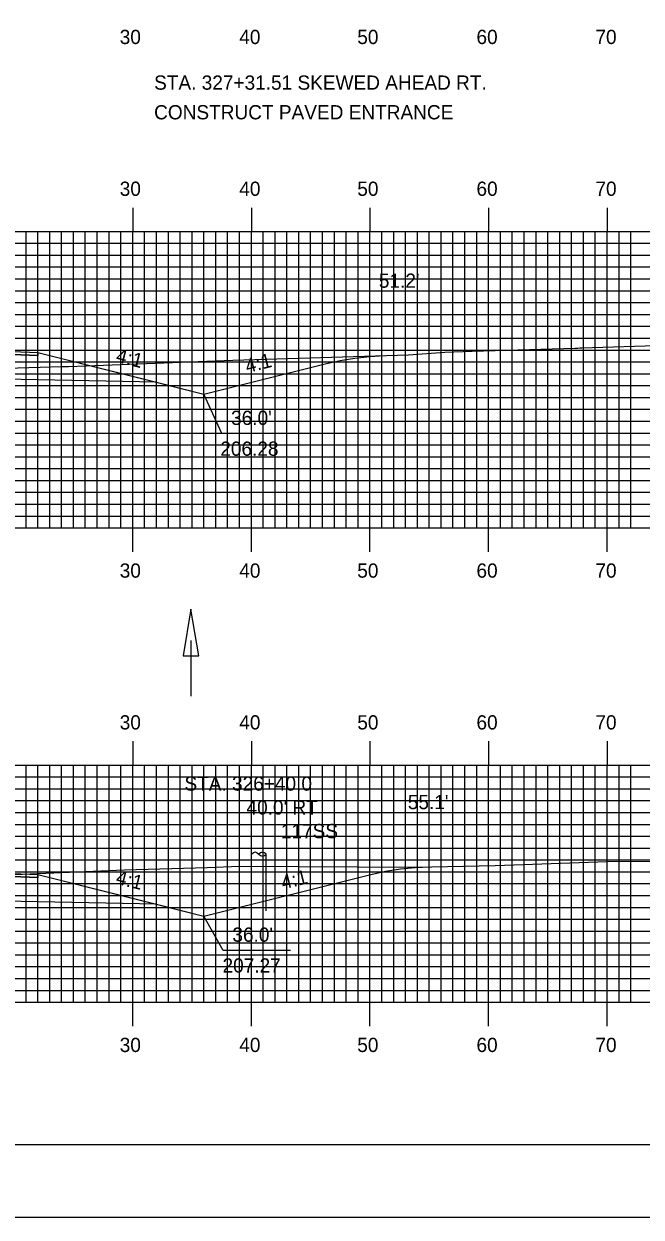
# Model space of a CAD drawing. Extents: x 1821605 to 1821948, y 442591 to 442811.
# Drawn here: x 1821791.6 to 1821843.6, y 442590.5 to 442691.2 of the extents above; entities that cross this region are included whole.
import ezdxf

# ---------------------------------------------------------------- set-up
doc = ezdxf.new("R2010")
doc.units = 0
for name, color, linetype in [('ANNOTATION', 7, 'Continuous'), ('BORDER', 7, 'Continuous'), ('D_Drainage_Ditch_Line', 7, 'Continuous'), ('D_Drainage_Text', 7, 'Continuous'), ('D_Roadway_Centerline', 7, 'Continuous'), ('D_Roadway_Edge_Shoulder', 7, 'Continuous'), ('D_Roadway_SlopeLines', 7, 'Continuous'), ('D_Roadway_SubGrade', 7, 'Continuous'), ('D_Text_Standard', 7, 'Continuous'), ('D_Utilities_Pole_Joint', 7, 'Continuous'), ('H_V ANNOTATION', 7, 'Continuous'), ('MAJOR', 7, 'Continuous'), ('MINOR', 7, 'Continuous'), ('PLOT BOUNDARY', 7, 'Continuous'), ('S_Roadway_Centerline', 7, 'Continuous')]:
    doc.layers.add(name, color=color, linetype=linetype)

msp = doc.modelspace()

# ---------------------------------------------------------------- linework, layer by layer
at = {"layer": 'ANNOTATION'}
for points in [[(1821813.95, 442656.62), (1821808.26, 442656.62), (1821806.74, 442659.95)], [(1821814.05, 442613.04), (1821808.36, 442613.04), (1821806.74, 442615.93)]]:
    msp.add_lwpolyline(points, dxfattribs=at)
at = {"layer": 'BORDER'}
msp.add_lwpolyline([(1821621.14, 442596.67), (1821941.14, 442596.67), (1821941.14, 442806.67), (1821621.14, 442806.67)], close=True, dxfattribs=at)
at = {"layer": 'D_Drainage_Ditch_Line'}
msp.add_line((1821805.65, 442639.18), (1821805.65, 442634.48), dxfattribs=at)
msp.add_lwpolyline([(1821805, 442637.87), (1821806.31, 442637.87), (1821805.65, 442641.81)], close=True, dxfattribs=at)
at = {"layer": 'D_Roadway_Centerline'}
for points in [[(1821726.4, 442659.78), (1821730.4, 442660.78), (1821740.74, 442663.37), (1821746.74, 442663.61), (1821770.74, 442664.09), (1821782.74, 442663.85), (1821792.74, 442663.45), (1821802.74, 442660.95), (1821806.74, 442659.95), (1821816.97, 442662.5), (1821818.22, 442662.78), (1821819.47, 442662.99), (1821820.72, 442663.13), (1821821.97, 442663.21)], [(1821726.4, 442615.77), (1821730.4, 442616.77), (1821740.74, 442619.35), (1821746.74, 442619.59), (1821770.74, 442620.07), (1821782.74, 442619.83), (1821792.74, 442619.43), (1821802.74, 442616.93), (1821806.74, 442615.93), (1821820.81, 442619.45), (1821822.06, 442619.72), (1821823.31, 442619.92), (1821824.56, 442620.04), (1821825.81, 442620.09)]]:
    msp.add_lwpolyline(points, dxfattribs=at)
at = {"layer": 'D_Roadway_Edge_Shoulder'}
for points in [[(1821782.74, 442663.85), (1821792.74, 442663.45), (1821792.74, 442663.2), (1821782.74, 442663.6)], [(1821782.74, 442619.83), (1821792.74, 442619.43), (1821792.74, 442619.18), (1821782.74, 442619.58)]]:
    msp.add_lwpolyline(points, close=True, dxfattribs=at)
at = {"layer": 'D_Roadway_SlopeLines'}
for points in [[(1821792.74, 442663.45), (1821806.74, 442659.95)], [(1821806.74, 442659.95), (1821816.97, 442662.5), (1821818.22, 442662.78), (1821819.47, 442662.99), (1821820.72, 442663.13), (1821821.97, 442663.21)], [(1821792.74, 442619.43), (1821806.74, 442615.93)], [(1821806.74, 442615.93), (1821820.81, 442619.45), (1821822.06, 442619.72), (1821823.31, 442619.92), (1821824.56, 442620.04), (1821825.81, 442620.09)]]:
    msp.add_lwpolyline(points, dxfattribs=at)
at = {"layer": 'D_Roadway_SubGrade'}
for points in [[(1821746.74, 442661.11), (1821730.4, 442660.78), (1821740.74, 442663.37), (1821740.74, 442663.12), (1821746.74, 442663.36), (1821770.74, 442663.84), (1821782.74, 442663.6), (1821792.74, 442663.2), (1821792.74, 442663.45), (1821802.74, 442660.95), (1821782.74, 442661.35), (1821770.74, 442661.59)], [(1821746.74, 442617.09), (1821730.4, 442616.77), (1821740.74, 442619.35), (1821740.74, 442619.1), (1821746.74, 442619.34), (1821770.74, 442619.82), (1821782.74, 442619.58), (1821792.74, 442619.18), (1821792.74, 442619.43), (1821802.74, 442616.93), (1821782.74, 442617.33), (1821770.74, 442617.57)]]:
    msp.add_lwpolyline(points, close=True, dxfattribs=at)
at = {"layer": 'D_Utilities_Pole_Joint'}
for p, q in [((1821810.74, 442621.15), (1821810.9, 442621.26)), ((1821811.21, 442621.26), (1821811.37, 442621.15)), ((1821811.52, 442621.26), (1821811.37, 442621.15)), ((1821811.99, 442621.15), (1821811.84, 442621.26)), ((1821810.74, 442616.39), (1821810.74, 442621.15)), ((1821811.37, 442621.15), (1821811.52, 442621.04)), ((1821811.84, 442621.04), (1821811.99, 442621.15)), ((1821811.99, 442616.39), (1821811.99, 442621.15))]:
    msp.add_line(p, q, dxfattribs=at)
for centre, start, end in [((1821811.06, 442621.04), 90, 125.2644), ((1821811.06, 442621.04), 54.7356, 90), ((1821811.68, 442621.04), 90, 125.2644), ((1821811.68, 442621.04), 54.7356, 90), ((1821811.68, 442621.26), 234.7356, 270), ((1821811.68, 442621.26), 270, 305.2644)]:
    msp.add_arc(centre, 0.271, start, end, dxfattribs=at)
at = {"layer": 'MAJOR'}
for p, q in [((1821800.74, 442675.67), (1821800.74, 442673.67)), ((1821810.74, 442675.67), (1821810.74, 442673.67)), ((1821820.74, 442675.67), (1821820.74, 442673.67)), ((1821830.74, 442675.67), (1821830.74, 442673.67)), ((1821840.74, 442675.67), (1821840.74, 442673.67)), ((1821630.74, 442673.67), (1821910.74, 442673.67)), ((1821630.74, 442673.67), (1821910.74, 442673.67)), ((1821800.74, 442648.67), (1821800.74, 442673.67)), ((1821810.74, 442648.67), (1821810.74, 442673.67)), ((1821820.74, 442648.67), (1821820.74, 442673.67)), ((1821830.74, 442648.67), (1821830.74, 442673.67)), ((1821840.74, 442648.67), (1821840.74, 442673.67)), ((1821630.74, 442668.67), (1821910.74, 442668.67)), ((1821630.74, 442663.67), (1821910.74, 442663.67)), ((1821630.74, 442658.67), (1821910.74, 442658.67)), ((1821630.74, 442653.67), (1821910.74, 442653.67)), ((1821630.74, 442648.67), (1821910.74, 442648.67)), ((1821630.74, 442648.67), (1821910.74, 442648.67)), ((1821800.74, 442646.66), (1821800.74, 442648.67)), ((1821810.74, 442646.66), (1821810.74, 442648.67)), ((1821820.74, 442646.66), (1821820.74, 442648.67)), ((1821830.74, 442646.66), (1821830.74, 442648.67)), ((1821840.74, 442646.66), (1821840.74, 442648.67)), ((1821800.74, 442630.67), (1821800.74, 442628.67)), ((1821810.74, 442630.67), (1821810.74, 442628.67)), ((1821820.74, 442630.67), (1821820.74, 442628.67)), ((1821830.74, 442630.67), (1821830.74, 442628.67)), ((1821840.74, 442630.67), (1821840.74, 442628.67)), ((1821630.74, 442628.67), (1821910.74, 442628.67)), ((1821630.74, 442628.67), (1821910.74, 442628.67)), ((1821800.74, 442608.67), (1821800.74, 442628.67)), ((1821810.74, 442608.67), (1821810.74, 442628.67)), ((1821820.74, 442608.67), (1821820.74, 442628.67)), ((1821830.74, 442608.67), (1821830.74, 442628.67)), ((1821840.74, 442608.67), (1821840.74, 442628.67)), ((1821630.74, 442623.67), (1821910.74, 442623.67)), ((1821630.74, 442618.67), (1821910.74, 442618.67)), ((1821630.74, 442613.67), (1821910.74, 442613.67)), ((1821630.74, 442608.67), (1821910.74, 442608.67)), ((1821630.74, 442608.67), (1821910.74, 442608.67)), ((1821800.74, 442606.66), (1821800.74, 442608.67)), ((1821810.74, 442606.66), (1821810.74, 442608.67)), ((1821820.74, 442606.66), (1821820.74, 442608.67)), ((1821830.74, 442606.66), (1821830.74, 442608.67)), ((1821840.74, 442606.66), (1821840.74, 442608.67))]:
    msp.add_line(p, q, dxfattribs=at)
at = {"layer": 'MINOR'}
for p, q in [((1821791.74, 442648.67), (1821791.74, 442673.67)), ((1821792.74, 442648.67), (1821792.74, 442673.67)), ((1821793.74, 442648.67), (1821793.74, 442673.67)), ((1821794.74, 442648.67), (1821794.74, 442673.67)), ((1821795.74, 442648.67), (1821795.74, 442673.67)), ((1821796.74, 442648.67), (1821796.74, 442673.67)), ((1821797.74, 442648.67), (1821797.74, 442673.67)), ((1821798.74, 442648.67), (1821798.74, 442673.67)), ((1821799.74, 442648.67), (1821799.74, 442673.67)), ((1821801.74, 442648.67), (1821801.74, 442673.67)), ((1821802.74, 442648.67), (1821802.74, 442673.67)), ((1821803.74, 442648.67), (1821803.74, 442673.67)), ((1821804.74, 442648.67), (1821804.74, 442673.67)), ((1821805.74, 442648.67), (1821805.74, 442673.67)), ((1821806.74, 442648.67), (1821806.74, 442673.67)), ((1821807.74, 442648.67), (1821807.74, 442673.67)), ((1821808.74, 442648.67), (1821808.74, 442673.67)), ((1821809.74, 442648.67), (1821809.74, 442673.67)), ((1821811.74, 442648.67), (1821811.74, 442673.67)), ((1821812.74, 442648.67), (1821812.74, 442673.67)), ((1821813.74, 442648.67), (1821813.74, 442673.67)), ((1821814.74, 442648.67), (1821814.74, 442673.67)), ((1821815.74, 442648.67), (1821815.74, 442673.67)), ((1821816.74, 442648.67), (1821816.74, 442673.67)), ((1821817.74, 442648.67), (1821817.74, 442673.67)), ((1821818.74, 442648.67), (1821818.74, 442673.67)), ((1821819.74, 442648.67), (1821819.74, 442673.67)), ((1821821.74, 442648.67), (1821821.74, 442673.67)), ((1821822.74, 442648.67), (1821822.74, 442673.67)), ((1821823.74, 442648.67), (1821823.74, 442673.67)), ((1821824.74, 442648.67), (1821824.74, 442673.67)), ((1821825.74, 442648.67), (1821825.74, 442673.67)), ((1821826.74, 442648.67), (1821826.74, 442673.67)), ((1821827.74, 442648.67), (1821827.74, 442673.67)), ((1821828.74, 442648.67), (1821828.74, 442673.67)), ((1821829.74, 442648.67), (1821829.74, 442673.67)), ((1821831.74, 442648.67), (1821831.74, 442673.67)), ((1821832.74, 442648.67), (1821832.74, 442673.67)), ((1821833.74, 442648.67), (1821833.74, 442673.67)), ((1821834.74, 442648.67), (1821834.74, 442673.67)), ((1821835.74, 442648.67), (1821835.74, 442673.67)), ((1821836.74, 442648.67), (1821836.74, 442673.67)), ((1821837.74, 442648.67), (1821837.74, 442673.67)), ((1821838.74, 442648.67), (1821838.74, 442673.67)), ((1821839.74, 442648.67), (1821839.74, 442673.67)), ((1821841.74, 442648.67), (1821841.74, 442673.67)), ((1821842.74, 442648.67), (1821842.74, 442673.67)), ((1821630.74, 442672.67), (1821910.74, 442672.67)), ((1821630.74, 442671.67), (1821910.74, 442671.67)), ((1821630.74, 442670.67), (1821910.74, 442670.67)), ((1821630.74, 442669.67), (1821910.74, 442669.67)), ((1821630.74, 442667.67), (1821910.74, 442667.67)), ((1821630.74, 442666.67), (1821910.74, 442666.67)), ((1821630.74, 442665.67), (1821910.74, 442665.67)), ((1821630.74, 442664.67), (1821910.74, 442664.67)), ((1821630.74, 442662.67), (1821910.74, 442662.67)), ((1821630.74, 442661.67), (1821910.74, 442661.67)), ((1821630.74, 442660.67), (1821910.74, 442660.67)), ((1821630.74, 442659.67), (1821910.74, 442659.67)), ((1821630.74, 442657.67), (1821910.74, 442657.67)), ((1821630.74, 442656.67), (1821910.74, 442656.67)), ((1821630.74, 442655.67), (1821910.74, 442655.67)), ((1821630.74, 442654.67), (1821910.74, 442654.67)), ((1821630.74, 442652.67), (1821910.74, 442652.67)), ((1821630.74, 442651.67), (1821910.74, 442651.67)), ((1821630.74, 442650.67), (1821910.74, 442650.67)), ((1821630.74, 442649.67), (1821910.74, 442649.67)), ((1821791.74, 442608.67), (1821791.74, 442628.67)), ((1821792.74, 442608.67), (1821792.74, 442628.67)), ((1821793.74, 442608.67), (1821793.74, 442628.67)), ((1821794.74, 442608.67), (1821794.74, 442628.67)), ((1821795.74, 442608.67), (1821795.74, 442628.67)), ((1821796.74, 442608.67), (1821796.74, 442628.67)), ((1821797.74, 442608.67), (1821797.74, 442628.67)), ((1821798.74, 442608.67), (1821798.74, 442628.67)), ((1821799.74, 442608.67), (1821799.74, 442628.67)), ((1821801.74, 442608.67), (1821801.74, 442628.67)), ((1821802.74, 442608.67), (1821802.74, 442628.67)), ((1821803.74, 442608.67), (1821803.74, 442628.67)), ((1821804.74, 442608.67), (1821804.74, 442628.67)), ((1821805.74, 442608.67), (1821805.74, 442628.67)), ((1821806.74, 442608.67), (1821806.74, 442628.67)), ((1821807.74, 442608.67), (1821807.74, 442628.67)), ((1821808.74, 442608.67), (1821808.74, 442628.67)), ((1821809.74, 442608.67), (1821809.74, 442628.67)), ((1821811.74, 442608.67), (1821811.74, 442628.67)), ((1821812.74, 442608.67), (1821812.74, 442628.67)), ((1821813.74, 442608.67), (1821813.74, 442628.67)), ((1821814.74, 442608.67), (1821814.74, 442628.67)), ((1821815.74, 442608.67), (1821815.74, 442628.67)), ((1821816.74, 442608.67), (1821816.74, 442628.67)), ((1821817.74, 442608.67), (1821817.74, 442628.67)), ((1821818.74, 442608.67), (1821818.74, 442628.67)), ((1821819.74, 442608.67), (1821819.74, 442628.67)), ((1821821.74, 442608.67), (1821821.74, 442628.67)), ((1821822.74, 442608.67), (1821822.74, 442628.67)), ((1821823.74, 442608.67), (1821823.74, 442628.67)), ((1821824.74, 442608.67), (1821824.74, 442628.67)), ((1821825.74, 442608.67), (1821825.74, 442628.67)), ((1821826.74, 442608.67), (1821826.74, 442628.67)), ((1821827.74, 442608.67), (1821827.74, 442628.67)), ((1821828.74, 442608.67), (1821828.74, 442628.67)), ((1821829.74, 442608.67), (1821829.74, 442628.67)), ((1821831.74, 442608.67), (1821831.74, 442628.67)), ((1821832.74, 442608.67), (1821832.74, 442628.67)), ((1821833.74, 442608.67), (1821833.74, 442628.67)), ((1821834.74, 442608.67), (1821834.74, 442628.67)), ((1821835.74, 442608.67), (1821835.74, 442628.67)), ((1821836.74, 442608.67), (1821836.74, 442628.67)), ((1821837.74, 442608.67), (1821837.74, 442628.67)), ((1821838.74, 442608.67), (1821838.74, 442628.67)), ((1821839.74, 442608.67), (1821839.74, 442628.67)), ((1821841.74, 442608.67), (1821841.74, 442628.67)), ((1821842.74, 442608.67), (1821842.74, 442628.67)), ((1821630.74, 442627.67), (1821910.74, 442627.67)), ((1821630.74, 442626.67), (1821910.74, 442626.67)), ((1821630.74, 442625.67), (1821910.74, 442625.67)), ((1821630.74, 442624.67), (1821910.74, 442624.67)), ((1821630.74, 442622.67), (1821910.74, 442622.67)), ((1821630.74, 442621.67), (1821910.74, 442621.67)), ((1821630.74, 442620.67), (1821910.74, 442620.67)), ((1821630.74, 442619.67), (1821910.74, 442619.67)), ((1821630.74, 442617.67), (1821910.74, 442617.67)), ((1821630.74, 442616.67), (1821910.74, 442616.67)), ((1821630.74, 442615.67), (1821910.74, 442615.67)), ((1821630.74, 442614.67), (1821910.74, 442614.67)), ((1821630.74, 442612.67), (1821910.74, 442612.67)), ((1821630.74, 442611.67), (1821910.74, 442611.67)), ((1821630.74, 442610.67), (1821910.74, 442610.67)), ((1821630.74, 442609.67), (1821910.74, 442609.67))]:
    msp.add_line(p, q, dxfattribs=at)
at = {"layer": 'PLOT BOUNDARY'}
msp.add_lwpolyline([(1821604.96, 442590.55), (1821944.96, 442590.55), (1821944.96, 442810.55), (1821604.96, 442810.55)], close=True, dxfattribs=at)
at = {"layer": 'S_Roadway_Centerline'}
for points in [[(1821714.85, 442661.05), (1821726.06, 442661.38), (1821736.11, 442661.34), (1821743.84, 442661.28), (1821747.03, 442661.33), (1821759.62, 442661.5), (1821767.67, 442661.77), (1821776.85, 442661.75), (1821792.93, 442662.21), (1821794.71, 442662.28), (1821795.33, 442662.29), (1821796.81, 442662.34), (1821809.19, 442662.8), (1821823.98, 442663.27), (1821827.05, 442663.48), (1821829.36, 442663.58), (1821838.04, 442663.82), (1821838.28, 442663.83), (1821838.43, 442663.84), (1821838.61, 442663.85), (1821845.71, 442664.08)], [(1821713.55, 442617.48), (1821722.12, 442617.92), (1821733, 442617.73), (1821739.02, 442617.69), (1821746.43, 442617.87), (1821752.67, 442618), (1821756.52, 442618.11), (1821763.01, 442618.66), (1821780.24, 442619.56), (1821790.77, 442619.43), (1821800.04, 442619.83), (1821807.01, 442620.04), (1821809.74, 442620.15), (1821824.61, 442620.07), (1821831.29, 442620.19), (1821840.74, 442620.53), (1821853.23, 442620.61)]]:
    msp.add_lwpolyline(points, dxfattribs=at)

# ---------------------------------------------------------------- texts
at = {"layer": 'ANNOTATION'}
for rotation, p in [(345.9638, (1821799.25, 442662.68)), (14.0362, (1821810.39, 442661.72)), (345.9638, (1821799.25, 442618.67)), (14.0362, (1821813.42, 442618.17))]:
    msp.add_text('4:1', height=1.2, rotation=rotation, dxfattribs=at).set_placement(p)
for s, p in [("36.0'", (1821809.03, 442657.35)), ('206.28', (1821808.12, 442654.75)), ("36.0'", (1821809.14, 442613.77)), ('207.27', (1821808.31, 442611.17))]:
    msp.add_text(s, height=1.2, dxfattribs=at).set_placement(p)
at = {"layer": 'D_Drainage_Text'}
for s, p in [('STA. 326+40.0', (1821805.1, 442626.51)), ("40.0' RT", (1821810.33, 442624.5)), ('117SS', (1821813.23, 442622.5))]:
    msp.add_text(s, height=1.2, dxfattribs=at).set_placement(p)
at = {"layer": 'D_Text_Standard'}
for s, p in [('STA. 327+31.51 SKEWED AHEAD RT.', (1821802.54, 442685.62)), ('CONSTRUCT PAVED ENTRANCE', (1821802.54, 442683.12)), ("51.2'", (1821821.49, 442668.92)), ("55.1'", (1821823.93, 442624.95))]:
    msp.add_text(s, height=1.2, dxfattribs=at).set_placement(p)
at = {"layer": 'H_V ANNOTATION'}
for s, p in [('30', (1821799.64, 442689.47)), ('40', (1821809.72, 442689.47)), ('50', (1821819.67, 442689.47)), ('60', (1821829.72, 442689.47)), ('70', (1821839.75, 442689.47)), ('30', (1821799.64, 442676.67)), ('40', (1821809.72, 442676.67)), ('50', (1821819.67, 442676.67)), ('60', (1821829.72, 442676.67)), ('70', (1821839.75, 442676.67)), ('30', (1821799.64, 442644.47)), ('40', (1821809.72, 442644.47)), ('50', (1821819.67, 442644.47)), ('60', (1821829.72, 442644.47)), ('70', (1821839.75, 442644.47)), ('30', (1821799.64, 442631.67)), ('40', (1821809.72, 442631.67)), ('50', (1821819.67, 442631.67)), ('60', (1821829.72, 442631.67)), ('70', (1821839.75, 442631.67)), ('30', (1821799.64, 442604.47)), ('40', (1821809.72, 442604.47)), ('50', (1821819.67, 442604.47)), ('60', (1821829.72, 442604.47)), ('70', (1821839.75, 442604.47))]:
    msp.add_text(s, height=1.2, dxfattribs=at).set_placement(p)

doc.saveas('drawing.dxf')
